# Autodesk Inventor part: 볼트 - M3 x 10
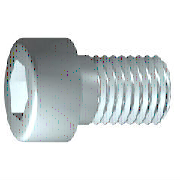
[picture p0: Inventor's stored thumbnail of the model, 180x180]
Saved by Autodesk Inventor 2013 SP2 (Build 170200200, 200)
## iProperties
Created: 2012-02
Part Number: 볼트 - M3 x 10
Material: 스테인리스강
Description: 6각 소켓 머리 캡 나사
Document SubType Name: Modeling
Standard: ISO 4762
Designer: mduedu
Standard Revision: Fourth edition 2004-03-01
Standards Organization: ISO
Language: ko-KR
Size Designation: M3 x 10
Categories: <MemberInstance><Categories><Category DisplayName="조임쇠" InternalName="e4da775c-781d-43d5-af7c-5136215cf5a6" Mnemonic="FSTN"><Category DisplayName="볼트" InternalN
Density: 8.08 g/cm^3
Mass: 1.0701 g
Surface Area: 2.01851 cm^2
Volume: 0.132438 cm^3
IsCustomPart: 0
Author: mduedu
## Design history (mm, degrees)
sketch "스케치1"
  geometry: L1 (-0.867, 0)-(10, 0); L2 (10, 0)-(10, 1.5); L3 (10, 1.5)-(1.25, 1.5); L4 (1.25, 1.5)-(0.943, 1.5); L5 (0.943, 1.5)-(0, 1.5); L6 (0, 1.5)-(0, 2.75); L7 (0, 2.75)-(-3, 2.75); L8 (-3, 2.75)-(-3, 1.443); L9 (-3, 1.443)-(-1.7, 1.443); L10 (-1.7, 1.443)-(-0.867, 0); L11 (-5.6, 0)-(12.6, 0) reference; L12 (0, -0.55)-(0, 3.3) reference; L13 (1.25, 1.5)-(0, 1.5)
  constraints: 22 end point, 6 parallel, 2 collinear, 2 perpendicular, 1 horizontal, 1 point on line
  dimensions: "d1" = 8.75 distance from line of L3.end L2 (= GEL); "d2" = 0.30683 distance of L4.end L3.end (computed from GAL); "d3" = 3 distance between parallel lines of L8 L6 (= KOH); "d4" = 1.3 distance of L8.end L9.end (= INTI); "d5" = 60 deg angle of L10 L1; "d6" = 3 diameter of L3 L1 (= GD); "d7" = 3 diameter of L5 L1 (= BDM); "d8" = 2.88675 diameter of L9 L1 (= 1.1547 x SW); "d9" = 5.5 diameter of L7 L1 (= KOD); "d26" = 10 distance between parallel lines of L12 L2 (= NLG)
revolve "본체" sketch "스케치1" stored, may be unused: angle "d10" = 90 deg
sketch "스케치2"
  geometry: L1 (0, -3.85)-(0, 3.85) reference; L2 (-3.85, 0)-(3.85, 0) reference; L3 (1.443, 0)-(0.722, -1.25); L4 (0.722, -1.25)-(-0.722, -1.25); L5 (-0.722, -1.25)-(-1.443, 0); L6 (-1.443, 0)-(-0.722, 1.25); L7 (-0.722, 1.25)-(0.722, 1.25); L8 (0.722, 1.25)-(1.443, 0); 2 further points
  constraints: 12 end point, 1 coincident, 1 horizontal alignment, 1 point on line, 12 other
extrude "슬롯" join sketch "스케치2" stored distance "d11" = 10; taper "d12" = 0 deg
workplane "Work Plane1"
fillet "Fillet2" dims "d30" = 0.1 (= R)
body "Solid1"
fillet "모깎기1" dims "d17" = 0.3 (= RR)
feature "스레드" dims "d13" = 8.75 (= GEL), "d14" = 0
chamfer "모따기1" distance "d15" = 0.30673 (= -0.5 x SPD + 0.5 x GD); stored, may be unused: second distance "d16" = 0.30673 (= GUL), angle "d27" = 45 deg
other parameters: "GD" = 3 [user parameter; used in 2 equation terms], "NLG" = 10 [user parameter; used in 1 equation term], "GEL" = 8.75 [user parameter; used in 2 equation terms], "KOD" = 5.5 [user parameter; used in 1 equation term], "KOH" = 3 [user parameter; used in 1 equation term], "INTI" = 1.3 [user parameter; used in 1 equation term], "GAL" = 0.30673 (= 0.61345 x PTC) [user parameter; used in 1 equation term], "GUL" = 0.30673 (= 0.61345 x PTC) [user parameter; used in 1 equation term], "BDM" = 3 (= NND) [user parameter; used in 1 equation term], "SW" = 2.5 [user parameter; used in 2 equation terms], "RR" = 0.3 [user parameter; used in 1 equation term], "SPD" = 2.38655 (= NND - 1.2269 x PTC) [user parameter; used in 1 equation term], "d19" = 0, "d28" = 0, "d29" = 0, "R" = 0.1 [user parameter; used in 1 equation term], "TOA" = 30 deg [user parameter], "GD1" = 2.38655 (= THREADDIA - 1.2269 x PTC) [user parameter], "THREADDIA" = 3 [user parameter; used in 1 equation term], "FAWI" = 45 deg [user parameter], "PTC" = 0.5 [user parameter; used in 5 equation terms], "NND" = 3 [user parameter; used in 2 equation terms], "E0" = 2.8875 (= 1.155 x SW) [user parameter]
